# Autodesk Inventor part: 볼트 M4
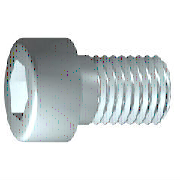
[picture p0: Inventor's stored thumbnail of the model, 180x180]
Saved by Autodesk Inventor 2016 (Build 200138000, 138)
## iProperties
IsCustomPart: 0
Created: 2012-02
Part Number: 볼트 M4
Material: 스테인리스강
Description: 6각 소켓 머리 캡 나사
Document SubType Name: Modeling
Standard: ISO 4762
Designer: mduedu
Standard Revision: Fourth edition 2004-03-01
Standards Organization: ISO
Language: ko-KR
Size Designation: M4 x 10
Categories: <MemberInstance><Categories><Category DisplayName="조임쇠" InternalName="e4da775c-781d-43d5-af7c-5136215cf5a6" Mnemonic="FSTN"><Category DisplayName="볼트" InternalN
Density: 7.75 g/cm^3
Appearance: 반광택
Author: mduedu
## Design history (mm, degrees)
sketch "스케치1"
  geometry: L1 (-1, 0)-(10, 0); L2 (10, 0)-(10, 2); L3 (10, 2)-(1.75, 2); L4 (1.75, 2)-(1.32, 2); L5 (1.32, 2)-(0, 2); L6 (0, 2)-(0, 3.5); L7 (0, 3.5)-(-4, 3.5); L8 (-4, 3.5)-(-4, 1.732); L9 (-4, 1.732)-(-2, 1.732); L10 (-2, 1.732)-(-1, 0); L11 (-6.8, 0)-(12.8, 0) reference; L12 (0, -0.7)-(0, 4.2) reference; L13 (1.75, 2)-(0, 2)
  constraints: 22 end point, 6 parallel, 2 collinear, 2 perpendicular, 1 horizontal, 1 point on line
  dimensions: "d1" = 8.25 distance from line of L3.end L2 (= GEL); "d2" = 0.42952 distance of L4.end L3.end (computed from GAL); "d3" = 4 distance between parallel lines of L8 L6 (= KOH); "d4" = 2 distance of L8.end L9.end (= INTI); "d5" = 60 deg angle of L10 L1; "d6" = 4 diameter of L3 L1 (= GD); "d7" = 4 diameter of L5 L1 (= BDM); "d8" = 3.4641 diameter of L9 L1 (= 1.1547 x SW); "d9" = 7 diameter of L7 L1 (= KOD); "d26" = 10 distance between parallel lines of L12 L2 (= NLG)
revolve "본체" sketch "스케치1" stored, may be unused: angle "d10" = 90 deg
sketch "스케치2"
  geometry: L1 (0, -4.9)-(0, 4.9) reference; L2 (-4.9, 0)-(4.9, 0) reference; L3 (1.732, 0)-(0.866, -1.5); L4 (0.866, -1.5)-(-0.866, -1.5); L5 (-0.866, -1.5)-(-1.732, 0); L6 (-1.732, 0)-(-0.866, 1.5); L7 (-0.866, 1.5)-(0.866, 1.5); L8 (0.866, 1.5)-(1.732, 0); 2 further points
  constraints: 12 end point, 1 coincident, 1 horizontal alignment, 1 point on line, 12 other
extrude "슬롯" join sketch "스케치2" stored distance "d11" = 10; taper "d12" = 0 deg
workplane "Work Plane1"
fillet "Fillet2" dims "d30" = 0.1 (= R)
body "Solid1"
fillet "모깎기1" dims "d17" = 0.4 (= RR)
feature "스레드" dims "d13" = 8.25 (= GEL), "d14" = 0
chamfer "모따기1" distance "d15" = 0.42941 (= -0.5 x SPD + 0.5 x GD); stored, may be unused: second distance "d16" = 0.42941 (= GUL), angle "d27" = 45 deg
other parameters: "GD" = 4 [user parameter; used in 2 equation terms], "NLG" = 10 [user parameter; used in 1 equation term], "GEL" = 8.25 [user parameter; used in 2 equation terms], "KOD" = 7 [user parameter; used in 1 equation term], "KOH" = 4 [user parameter; used in 1 equation term], "INTI" = 2 [user parameter; used in 1 equation term], "GAL" = 0.42941 (= 0.61345 x PTC) [user parameter; used in 1 equation term], "GUL" = 0.42941 (= 0.61345 x PTC) [user parameter; used in 1 equation term], "BDM" = 4 (= NND) [user parameter; used in 1 equation term], "SW" = 3 [user parameter; used in 2 equation terms], "RR" = 0.4 [user parameter; used in 1 equation term], "SPD" = 3.14117 (= NND - 1.2269 x PTC) [user parameter; used in 1 equation term], "d19" = 0, "d28" = 0, "d29" = 0, "R" = 0.1 [user parameter; used in 1 equation term], "TOA" = 30 deg [user parameter], "GD1" = 3.14117 (= THREADDIA - 1.2269 x PTC) [user parameter], "THREADDIA" = 4 [user parameter; used in 1 equation term], "FAWI" = 45 deg [user parameter], "TPU" = 14.28571 (computed from PTC) [user parameter], "PTC" = 0.7 [user parameter; used in 5 equation terms], "NND" = 4 [user parameter; used in 2 equation terms], "E0" = 3.465 (= 1.155 x SW) [user parameter]
